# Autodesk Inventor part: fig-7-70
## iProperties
Shininess: 64.0
Length Units: 11269
Angle Units: 11279
Time Units: 11290
Mass Units: 11283
Length Display Precision: 3
Angle Display Precision: 2
Compacted: True
Part Number: fig-7-70
Document SubType Name: Modeling
Created: 2002-12
Designer: deepak
Density: 0.0
Volumn: 0.0
Area: 0.0
PropertySet Name: Model Information
Control State: 0
Master: False
Checked Out: False
Author: deepak
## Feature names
1. Extrusion1
